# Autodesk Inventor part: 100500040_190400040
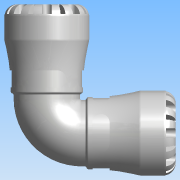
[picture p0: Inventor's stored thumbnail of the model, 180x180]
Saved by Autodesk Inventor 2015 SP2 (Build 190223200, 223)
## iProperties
Created: 2016-12
Part Number: 100500040_190400040
Material: PVC-Piping
Description: PLASSON 90° ELBOW 40X40 SERIES 1
Document SubType Name: Modeling
Designer: KIM
Mass: 664.223 g
Surface Area: 733.008 cm^2
Volume: 474.445 cm^3
Density: 1.4 g/cm^3
Appearance: Smooth - White
Author: KIM
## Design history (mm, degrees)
derived "1005.ipt"
feature "Solid1::1005.ipt"
tag "TaggingFeature1"
body "Solid1"
other parameters: "d1" = 29.4, "d8" = 59.5, "d13" = 8, "d14" = 8, "d15" = 0, "d17" = 360 deg, "d19" = 8 deg, "d20" = 0.8, "d21" = 0.8, "d22" = 8 deg, "d24" = 0, "d26" = 360 deg, "d33" = 7, "d43" = 54.6, "d51" = 0.7, "d54" = 14, "d55" = 8.8, "d57" = 15.68, "d58" = 0, "d74" = 0, "d77" = 3.33333, "d82" = 0.8, "d115" = 360 deg, "d207" = 90 deg, "d228" = 11.9, "d247" = 1.4, "d248" = 4.2, "d268" = 32.725, "d269" = 4.2, "d270" = 106, "d272" = 90 deg, "d274" = 0, "d275" = 0, "A_" = 106
